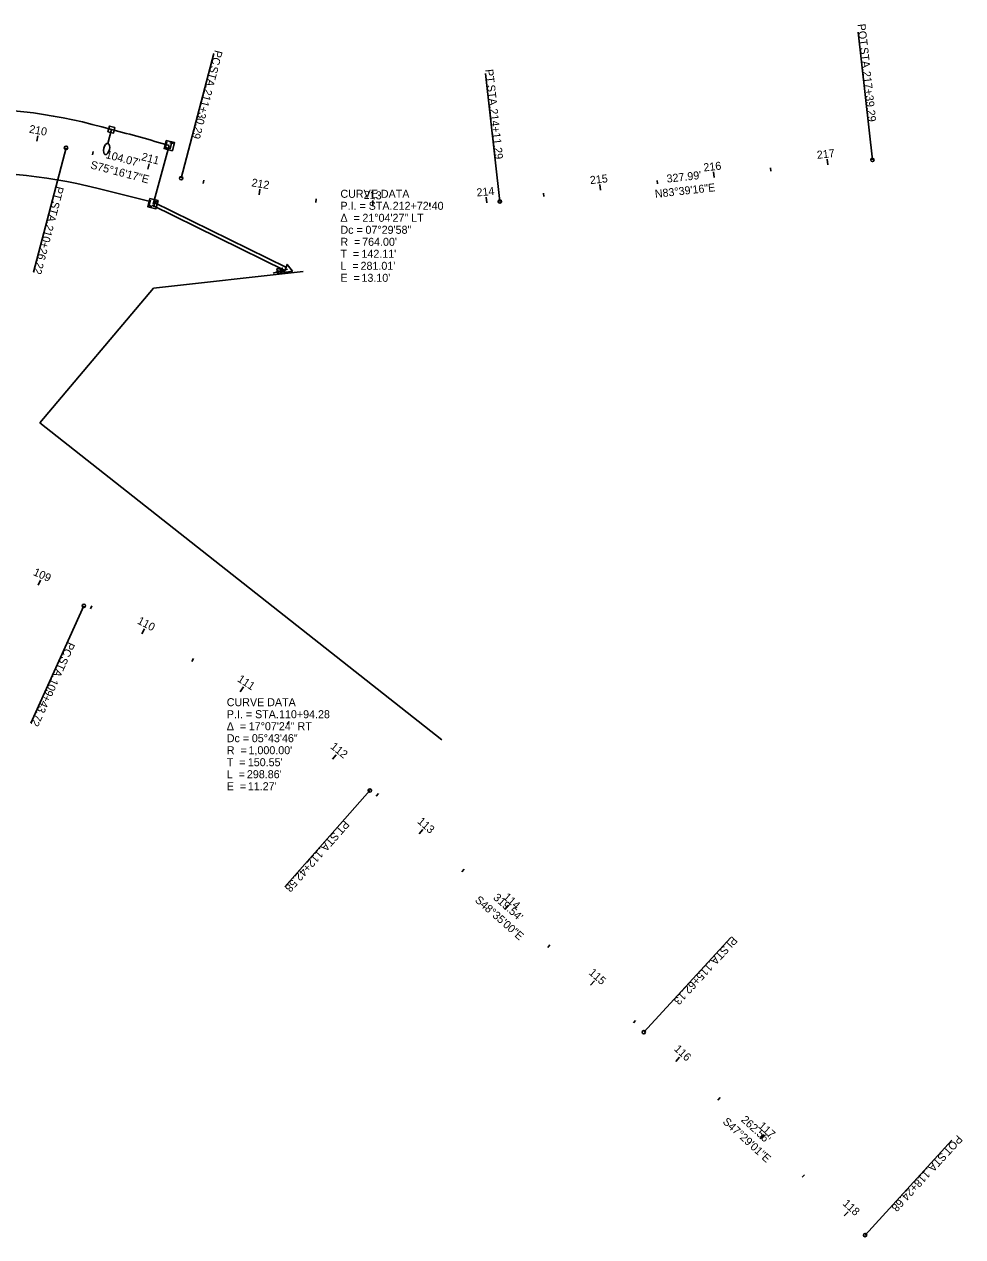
# Model space of a CAD drawing. Extents: x 1598538 to 1602183, y 285823 to 288192.
# Drawn here: x 1601362 to 1602183, y 285823 to 286884 of the extents above; entities that cross this region are included whole.
import ezdxf

# ---------------------------------------------------------------- set-up
doc = ezdxf.new("R2010")
doc.units = 0
for name, color, linetype in [('_CIVIL_CONSTRUCTION', 7, 'Continuous'), ('CM_Corridor_Conceptual', 7, 'Continuous'), ('CM_Corridor_Range_Conceptual', 7, 'Continuous'), ('MD_P_ACSC_B', 7, 'Continuous'), ('MD_P_ACSC_T', 7, 'Continuous'), ('MD_P_AGB_B', 7, 'Continuous'), ('PV_P_Curb', 7, 'Continuous'), ('PV_P_EOP', 7, 'Continuous'), ('RW_P_Esmt_LA', 7, 'Continuous'), ('RW_P_Esmt_SH', 7, 'Continuous'), ('RW_P_Esmt_TMP', 7, 'Continuous'), ('RW_P_Fee_RW', 7, 'Continuous')]:
    doc.layers.add(name, color=color, linetype=linetype)

msp = doc.modelspace()

# ---------------------------------------------------------------- linework, layer by layer
at = {"layer": '_CIVIL_CONSTRUCTION'}
msp.add_lwpolyline([(1601589, 286666.7), (1601596.3, 286667.8), (1601591.7, 286673.7)], close=True, dxfattribs=at)
at = {"layer": 'MD_P_ACSC_B'}
msp.add_line((1601474.7, 286653), (1601605.8, 286667.6), dxfattribs=at)
at = {"layer": 'MD_P_ACSC_T'}
for q in [(1601474.7, 286653), (1601726.9, 286258)]:
    msp.add_line((1601375.5, 286535.2), q, dxfattribs=at)
at = {"layer": 'MD_P_AGB_B'}
for p, q in [((1601372.7, 286781.4), (1601373.6, 286786.3)), ((1601421.3, 286769.7), (1601422.1, 286772.6)), ((1601469.7, 286756.9), (1601471, 286761.8)), ((1602014.9, 286755.2), (1602014.6, 286758.2)), ((1602064.6, 286760.7), (1602064, 286765.7)), ((1601518.1, 286744.5), (1601518.8, 286747.4)), ((1601915.5, 286744.2), (1601915.2, 286747.1)), ((1601965.2, 286749.7), (1601964.6, 286754.7)), ((1601567.1, 286734.6), (1601567.9, 286739.6)), ((1601816.1, 286733.1), (1601815.8, 286736.1)), ((1601865.8, 286738.6), (1601865.3, 286743.6)), ((1601616.7, 286728), (1601617, 286731)), ((1601666.5, 286724.6), (1601666.7, 286729.6)), ((1601716.5, 286724.5), (1601716.4, 286727.5)), ((1601766.4, 286727.7), (1601765.9, 286732.6)), ((1601374, 286393.1), (1601376.1, 286397.6)), ((1601419.6, 286372.5), (1601420.8, 286375.2)), ((1601464.5, 286350.5), (1601466.8, 286354.9)), ((1601508.2, 286326.3), (1601509.8, 286328.9)), ((1601550.7, 286299.9), (1601553.5, 286304.1)), ((1601591.8, 286271.5), (1601593.6, 286273.9)), ((1601631.5, 286241), (1601634.6, 286244.9)), ((1601669.6, 286208.6), (1601671.6, 286210.9)), ((1601707.1, 286175.6), (1601710.4, 286179.3)), ((1601744.6, 286142.5), (1601746.5, 286144.7)), ((1601782.1, 286109.4), (1601785.4, 286113.2)), ((1601819.6, 286076.3), (1601821.5, 286078.6)), ((1601857.1, 286043.3), (1601860.4, 286047)), ((1601894.5, 286010.2), (1601896.5, 286012.4)), ((1601931.6, 285976.6), (1601934.9, 285980.3)), ((1601968.4, 285942.8), (1601970.4, 285945)), ((1602005.3, 285909), (1602008.6, 285912.7)), ((1602042.1, 285875.2), (1602044.1, 285877.4)), ((1602079, 285841.4), (1602082.4, 285845.1))]:
    msp.add_line(p, q, dxfattribs=at)
at = {"layer": 'PV_P_Curb'}
for p, q in [((1602103.6, 286765.1), (1602091.2, 286876.9)), ((1601499, 286749.2), (1601527.6, 286858.1)), ((1601777.7, 286728.8), (1601765.2, 286840.6)), ((1601398.3, 286775.7), (1601369.7, 286666.9)), ((1601413.9, 286375.1), (1601367.6, 286272.5)), ((1601664, 286213.5), (1601589.6, 286129.2)), ((1601903.6, 286002.2), (1601979.7, 286085.1)), ((1602097.2, 285824.7), (1602173.2, 285907.6))]:
    msp.add_line(p, q, dxfattribs=at)
for centre in [(1601398.3, 286775.7), (1602103.6, 286765.1), (1601499, 286749.2), (1601777.7, 286728.8), (1601413.9, 286375.1), (1601664, 286213.5), (1601903.6, 286002.2), (1602097.2, 285824.7)]:
    msp.add_circle(centre, 1.5, dxfattribs=at)
at = {"layer": 'RW_P_Esmt_LA'}
msp.add_line((1601438.1, 286791.6), (1601435, 286779.5), dxfattribs=at)
msp.add_lwpolyline([(1601441.1, 286793.5), (1601439.9, 286788.6), (1601435, 286789.8), (1601436.3, 286794.7)], close=True, dxfattribs=at)
msp.add_ellipse((1601433.8, 286774.7), major_axis=(-1.21, -4.85), ratio=0.5, dxfattribs=at)
at = {"layer": 'RW_P_Esmt_SH'}
msp.add_line((1601474.4, 286726.5), (1601488.6, 286777.7), dxfattribs=at)
at = {"layer": 'RW_P_Esmt_TMP'}
for p, q in [((1601438.1, 286791.6), (1601438.1, 286791.6)), ((1601425.3, 286740.5), (1601471.9, 286728.7)), ((1601589.8, 286668.4), (1601473.5, 286725.6)), ((1601591.1, 286671.1), (1601474.9, 286728.3)), ((1601579.4, 286666), (1601585.4, 286667.8)), ((1601591.9, 286669.5), (1601585.4, 286667.8))]:
    msp.add_line(p, q, dxfattribs=at)
for centre, radius, start, end in [((1601309.5, 286355.9), 454.3, 73.5556, 108.674), ((1601102, 285478.5), 1355.5, 73.4278, 75.6431), ((1601301.5, 286221.5), 533.6, 76.5827, 91.9701)]:
    msp.add_arc(centre, radius, start, end, dxfattribs=at)
at = {"layer": 'RW_P_Fee_RW'}
for p, q in [((1601488.6, 286777.7), (1601488.6, 286777.7)), ((1601474.2, 286726.9), (1601474.2, 286726.9)), ((1601585.4, 286667.8), (1601585.4, 286667.8))]:
    msp.add_line(p, q, dxfattribs=at)
for points in [[(1601485.9, 286782.2), (1601493.1, 286780.4), (1601491.3, 286773.1), (1601484, 286775)], [(1601471.5, 286731.5), (1601478.8, 286729.6), (1601476.9, 286722.4), (1601469.7, 286724.2)], [(1601582.7, 286669.8), (1601587.4, 286670.5), (1601588.2, 286665.9), (1601583.5, 286665.1)]]:
    msp.add_lwpolyline(points, close=True, dxfattribs=at)
for points in [[(1601486.6, 286780.8), (1601485.3, 286775.9), (1601488, 286775.2)], [(1601489.1, 286780.1), (1601492.1, 286779.4)], [(1601490.6, 286779.7), (1601489.4, 286774.9)], [(1601472.2, 286730), (1601471, 286725.2), (1601473.6, 286724.5)], [(1601474.7, 286729.4), (1601477.7, 286728.6)], [(1601476.2, 286729), (1601475, 286724.1)], [(1601583.5, 286669.1), (1601584, 286666), (1601585.7, 286666.3)], [(1601585.1, 286669.4), (1601587.1, 286669.7)], [(1601586.1, 286669.5), (1601586.6, 286666.4)]]:
    msp.add_lwpolyline(points, dxfattribs=at)

# ---------------------------------------------------------------- texts
at = {"layer": 'CM_Corridor_Conceptual'}
for s, p in [('CURVE DATA', (1601638.3, 286732)), ('P.I. = STA. ', (1601638.3, 286721.5)), ('212+72.40', (1601684, 286721.5)), ('Δ  = ', (1601638.3, 286711)), ('21°04\'27" LT', (1601657.5, 286711)), ('Dc = ', (1601638.3, 286700.5)), ('07°29\'58"', (1601660.2, 286700.5)), ('R  = ', (1601638.3, 286690)), ("764.00'", (1601657.3, 286690)), ('T  = ', (1601638.3, 286679.5)), ("142.11'", (1601656.7, 286679.5)), ('L  = ', (1601638.3, 286669)), ("281.01'", (1601655.9, 286669)), ('E  = ', (1601638.3, 286658.5)), ("13.10'", (1601656.7, 286658.5)), ('CURVE DATA', (1601538.9, 286287.3)), ('P.I. = STA. ', (1601538.9, 286276.8)), ('110+94.28', (1601584.6, 286276.8)), ('Δ  = ', (1601538.9, 286266.3)), ('17°07\'24" RT', (1601558.1, 286266.3)), ('Dc = ', (1601538.9, 286255.8)), ('05°43\'46"', (1601560.8, 286255.8)), ('R  = ', (1601538.9, 286245.3)), ("1,000.00'", (1601557.9, 286245.3)), ('T  = ', (1601538.9, 286234.8)), ("150.55'", (1601557.3, 286234.8)), ('L  = ', (1601538.9, 286224.3)), ("298.86'", (1601556.5, 286224.3)), ('E  = ', (1601538.9, 286213.8)), ("11.27'", (1601557.3, 286213.8))]:
    msp.add_text(s, height=7, dxfattribs=at).set_placement(p)
at = {"layer": 'CM_Corridor_Range_Conceptual'}
for s, rotation, p in [("104.07'", 345.2715, (1601432.5, 286766.8)), ("327.99'", 6.3456, (1601924, 286745.2)), ("319.54'", 318.5834, (1601771.4, 286119)), ("262.56'", 317.4836, (1601988.2, 285924.8))]:
    msp.add_text(s, height=7, rotation=rotation, dxfattribs=at).set_placement(p)
at = {"layer": 'MD_P_AGB_B'}
for s, rotation, p in [('210', 349.6896, (1601365.6, 286789)), ('211', 345.2715, (1601463.7, 286765)), ('217', 6.3456, (1602055.4, 286766)), ('216', 6.3456, (1601956.2, 286755)), ('212', 350.4996, (1601560.1, 286742.1)), ('215', 6.3456, (1601856.9, 286743.9)), ('213', 357.9991, (1601658.6, 286731.1)), ('214', 5.4985, (1601757.7, 286733.1)), ('109', 335.7068, (1601369, 286402.2)), ('110', 332.4824, (1601460, 286359.9)), ('111', 326.7529, (1601547.6, 286309.5)), ('112', 321.0233, (1601629, 286251)), ('113', 318.5834, (1601705.1, 286185.7)), ('114', 318.5834, (1601780.1, 286119.5)), ('115', 318.5834, (1601855, 286053.4)), ('116', 317.4836, (1601929.6, 285986.8)), ('117', 317.4836, (1602003.2, 285919.4)), ('118', 317.4836, (1602077.1, 285851.6))]:
    msp.add_text(s, height=7, rotation=rotation, dxfattribs=at).set_placement(p)
at = {"layer": 'PV_P_Curb'}
for s, rotation, p in [('POT', 276.3456, (1602090.5, 286883.8)), (' STA. ', 276.3456, (1602092.5, 286865.9)), ('PC', 255.2715, (1601528.6, 286861.6)), (' STA. ', 255.2715, (1601525.7, 286850.5)), ('PT', 276.3456, (1601764.9, 286844.1)), ('217+39.29', 276.3456, (1602095.1, 286842.4)), ('211+30.29', 255.2715, (1601519.7, 286827.6)), (' STA. ', 276.3456, (1601766.2, 286833.1)), ('214+11.29', 276.3456, (1601768.8, 286809.6)), ('PT', 255.2715, (1601389.7, 286742.6)), (' STA. ', 255.2715, (1601386.9, 286732)), ('210+26.22', 255.2715, (1601380.9, 286709.1)), ('PC', 245.7068, (1601400, 286344.1)), (' STA. ', 245.7068, (1601395.3, 286333.7)), ('109+43.72', 245.7068, (1601385.6, 286312.1)), ('PT', 228.5834, (1601641.6, 286188)), (' STA. ', 228.5834, (1601634.3, 286179.7)), ('112+42.58', 228.5834, (1601618.7, 286162)), ('PI', 227.4836, (1601981.1, 286086.5)), (' STA. ', 227.4836, (1601975.4, 286080.3)), ('115+62.13', 227.4836, (1601959.4, 286062.9)), ('POT', 227.4836, (1602178, 285912.7)), (' STA. ', 227.4836, (1602165.8, 285899.4)), ('118+24.68', 227.4836, (1602149.8, 285882))]:
    msp.add_text(s, height=7, rotation=rotation, dxfattribs=at).set_placement(p)
at = {"layer": 'PV_P_EOP'}
for s, rotation, p in [('S75°16\'17"E', 345.2715, (1601419.1, 286757.8)), ('N83°39\'16"E', 6.3456, (1601913.7, 286731.9)), ('S48°35\'00"E', 318.5834, (1601755.4, 286116.9)), ('S47°29\'01"E', 317.4836, (1601972.1, 285923.1))]:
    msp.add_text(s, height=7, rotation=rotation, dxfattribs=at).set_placement(p)

doc.saveas('drawing.dxf')
